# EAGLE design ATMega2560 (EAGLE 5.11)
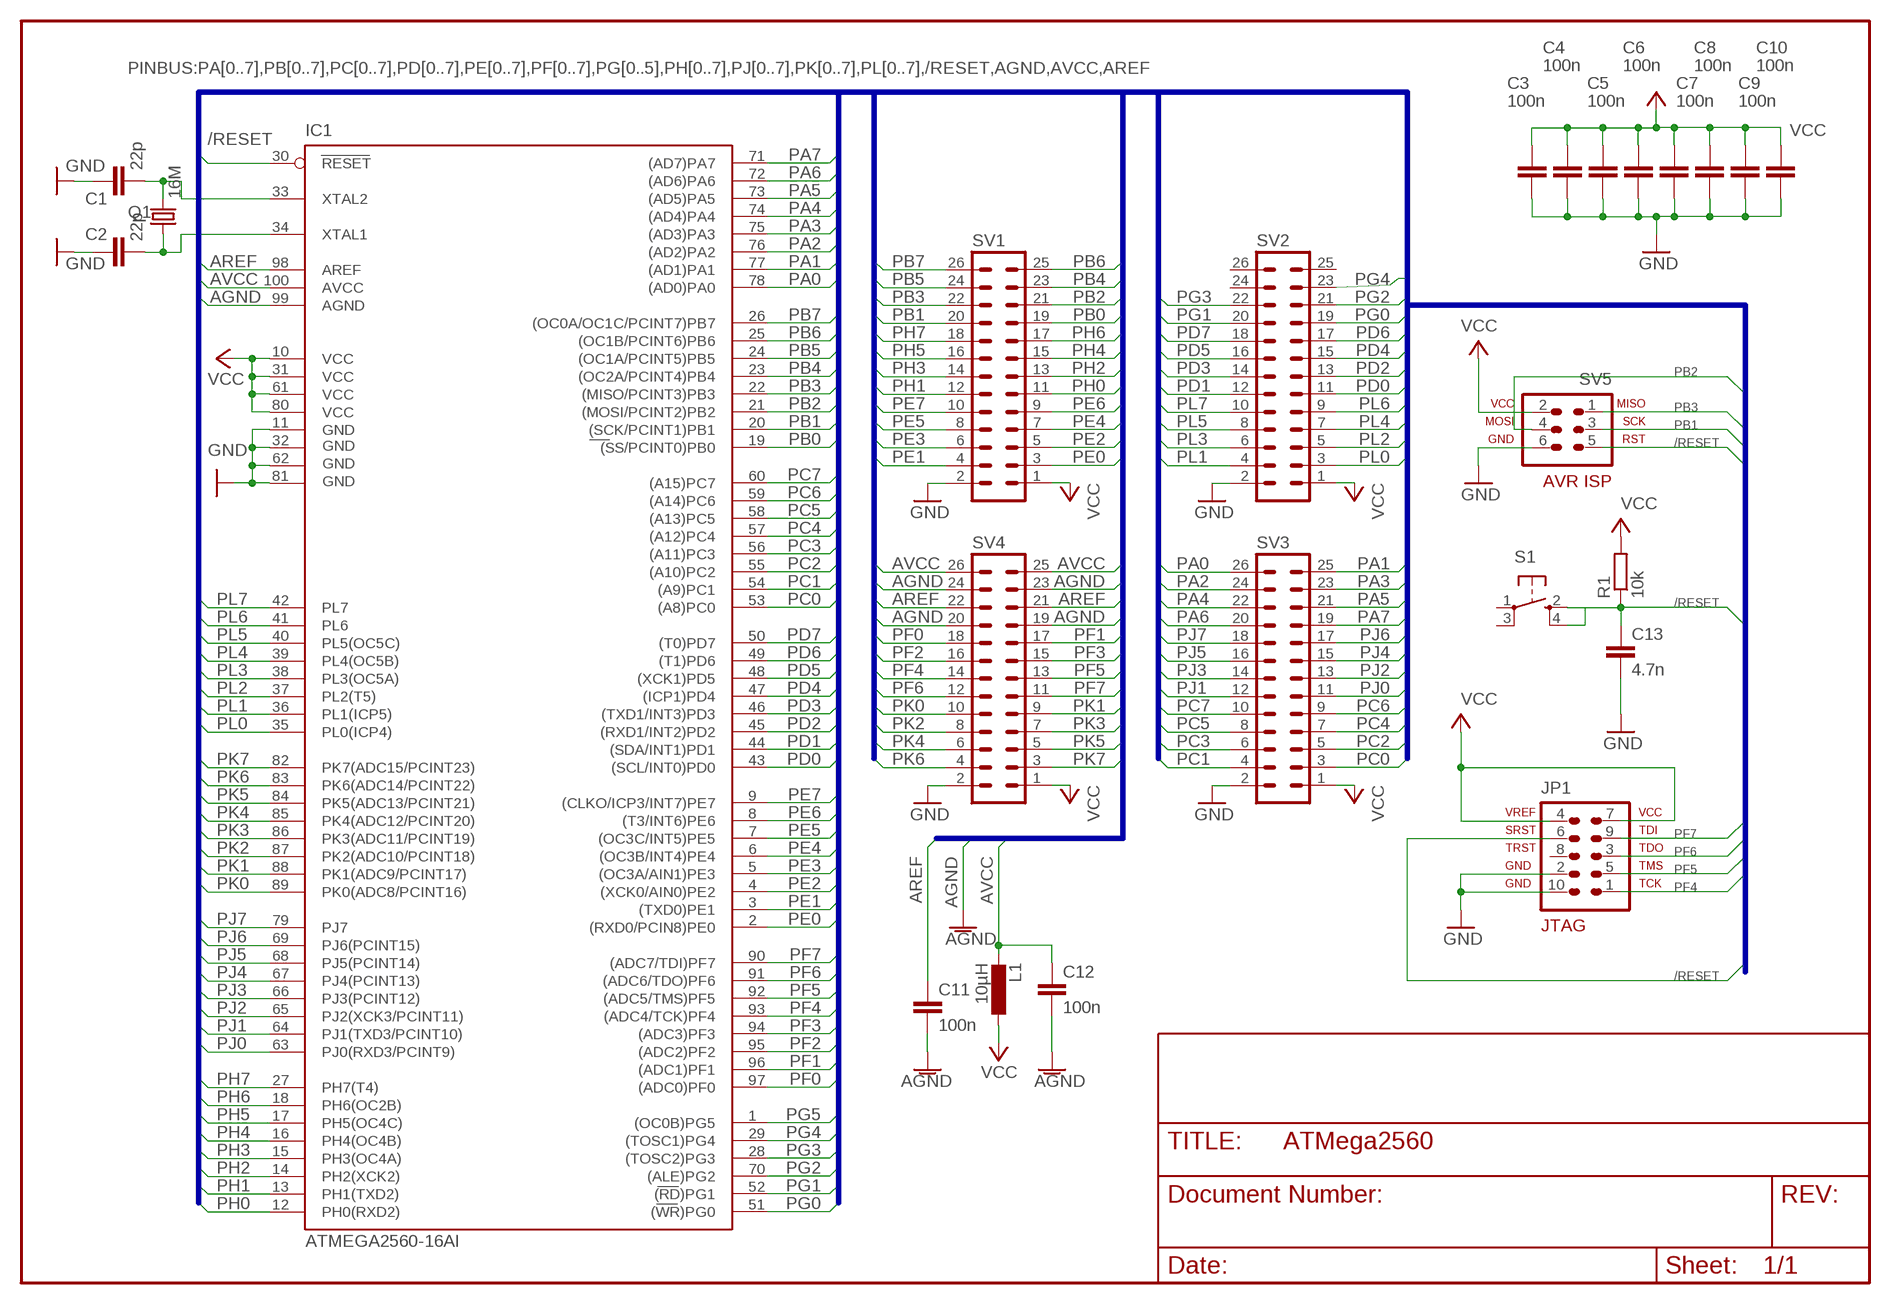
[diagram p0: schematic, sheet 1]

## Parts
C1  22p  C-EUC0402  [C0402]
C2  22p  C-EUC0402  [C0402]
C3  100n  C-EUC0402  [C0402]
C4  100n  C-EUC0402  [C0402]
C5  100n  C-EUC0402  [C0402]
C6  100n  C-EUC0402  [C0402]
C7  100n  C-EUC0402  [C0402]
C8  100n  C-EUC0402  [C0402]
C9  100n  C-EUC0402  [C0402]
C10  100n  C-EUC0402  [C0402]
C11  100n  C-EUC0402  [C0402]
C12  100n  C-EUC0402  [C0402]
C13  4.7n  C-EUC0402  [C0402]
IC1  ATMEGA2560-16AI  [TQFP100]
JP1  AVR-JTAG-10-R  [AVR-JTAG-10R]
L1  10µH  L-EUL1812  [L1812]
Q1  16M  CRYTALHC49S  [HC49/S]
R1  10k  R-EU_R0805  [R0805]
S1  10-XX  [B3S-1XXX]
SV1  MA13-2  [MA13-2]
SV2  MA13-2  [MA13-2]
SV3  MA13-2  [MA13-2]
SV4  MA13-2  [MA13-2]
SV5  AVR-ISP-6HORZ  [AVR-ISP-6R]

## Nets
/RESET: C13.1 IC1.30(RESET) JP1.6 R1.1 S1.2 S1.4 SV5.5
AGND: C11.2 C12.2 IC1.99(AGND) SV4.19 SV4.20 SV4.23 SV4.24
AREF: C11.1 IC1.98(AREF) SV4.21 SV4.22
AVCC: C12.1 IC1.100(AVCC) L1.2 SV4.25 SV4.26
GND: C1.1 C2.1 C3.2 C4.2 C5.2 C6.2 C7.2 C8.2 C9.2 C10.2 C13.2 IC1.11(GND) IC1.32(GND1) IC1.62(GND2) IC1.81(GND3) JP1.2 JP1.10 SV1.2 SV2.2 SV3.2 SV4.2 SV5.6
N$1: C1.2 IC1.33(XTAL2) Q1.2
N$2: C2.2 IC1.34(XTAL1) Q1.1
PA0: IC1.78((AD0)PA0) SV3.26
PA1: IC1.77((AD1)PA1) SV3.25
PA2: IC1.76((AD2)PA2) SV3.24
PA3: IC1.75((AD3)PA3) SV3.23
PA4: IC1.74((AD4)PA4) SV3.22
PA5: IC1.73((AD5)PA5) SV3.21
PA6: IC1.72((AD6)PA6) SV3.20
PA7: IC1.71((AD7)PA7) SV3.19
PB0: IC1.19((SS/PCINT0)PB0) SV1.19
PB1: IC1.20((SCK/PCINT1)PB1) SV1.20 SV5.3
PB2: IC1.21((MOSI/PCINT2)PB2) SV1.21 SV5.4
PB3: IC1.22((MISO/PCINT3)PB3) SV1.22 SV5.1
PB4: IC1.23((OC2A/PCINT4)PB4) SV1.23
PB5: IC1.24((OC1A/PCINT5)PB5) SV1.24
PB6: IC1.25((OC1B/PCINT6)PB6) SV1.25
PB7: IC1.26((OC0A/OC1C/PCINT7)PB7) SV1.26
PC0: IC1.53((A8)PC0) SV3.3
PC1: IC1.54((A9)PC1) SV3.4
PC2: IC1.55((A10)PC2) SV3.5
PC3: IC1.56((A11)PC3) SV3.6
PC4: IC1.57((A12)PC4) SV3.7
PC5: IC1.58((A13)PC5) SV3.8
PC6: IC1.59((A14)PC6) SV3.9
PC7: IC1.60((A15)PC7) SV3.10
PD0: IC1.43((SCL/INT0)PD0) SV2.11
PD1: IC1.44((SDA/INT1)PD1) SV2.12
PD2: IC1.45((RXD1/INT2)PD2) SV2.13
PD3: IC1.46((TXD1/INT3)PD3) SV2.14
PD4: IC1.47((ICP1)PD4) SV2.15
PD5: IC1.48((XCK1)PD5) SV2.16
PD6: IC1.49((T1)PD6) SV2.17
PD7: IC1.50((T0)PD7) SV2.18
PE0: IC1.2((RXD0/PCIN8)PE0) SV1.3
PE1: IC1.3((TXD0)PE1) SV1.4
PE2: IC1.4((XCK0/AIN0)PE2) SV1.5
PE3: IC1.5((OC3A/AIN1)PE3) SV1.6
PE4: IC1.6((OC3B/INT4)PE4) SV1.7
PE5: IC1.7((OC3C/INT5)PE5) SV1.8
PE6: IC1.8((T3/INT6)PE6) SV1.9
PE7: IC1.9((CLKO/ICP3/INT7)PE7) SV1.10
PF0: IC1.97((ADC0)PF0) SV4.18
PF1: IC1.96((ADC1)PF1) SV4.17
PF2: IC1.95((ADC2)PF2) SV4.16
PF3: IC1.94((ADC3)PF3) SV4.15
PF4: IC1.93((ADC4/TCK)PF4) JP1.1 SV4.14
PF5: IC1.92((ADC5/TMS)PF5) JP1.5 SV4.13
PF6: IC1.91((ADC6/TDO)PF6) JP1.3 SV4.12
PF7: IC1.90((ADC7/TDI)PF7) JP1.9 SV4.11
PG0: IC1.51((WR)PG0) SV2.19
PG1: IC1.52((RD)PG1) SV2.20
PG2: IC1.70((ALE)PG2) SV2.21
PG3: IC1.28((TOSC2)PG3) SV2.22
PG4: IC1.29((TOSC1)PG4) SV2.23
PG5: IC1.1((OC0B)PG5)
PH0: IC1.12(PH0(RXD2)) SV1.11
PH1: IC1.13(PH1(TXD2)) SV1.12
PH2: IC1.14(PH2(XCK2)) SV1.13
PH3: IC1.15(PH3(OC4A)) SV1.14
PH4: IC1.16(PH4(OC4B)) SV1.15
PH5: IC1.17(PH5(OC4C)) SV1.16
PH6: IC1.18(PH6(OC2B)) SV1.17
PH7: IC1.27(PH7(T4)) SV1.18
PJ0: IC1.63(PJ0(RXD3/PCINT9)) SV3.11
PJ1: IC1.64(PJ1(TXD3/PCINT10)) SV3.12
PJ2: IC1.65(PJ2(XCK3/PCINT11)) SV3.13
PJ3: IC1.66(PJ3(PCINT12)) SV3.14
PJ4: IC1.67(PJ4(PCINT13)) SV3.15
PJ5: IC1.68(PJ5(PCINT14)) SV3.16
PJ6: IC1.69(PJ6(PCINT15)) SV3.17
PJ7: IC1.79(PJ7) SV3.18
PK0: IC1.89(PK0(ADC8/PCINT16)) SV4.10
PK1: IC1.88(PK1(ADC9/PCINT17)) SV4.9
PK2: IC1.87(PK2(ADC10/PCINT18)) SV4.8
PK3: IC1.86(PK3(ADC11/PCINT19)) SV4.7
PK4: IC1.85(PK4(ADC12/PCINT20)) SV4.6
PK5: IC1.84(PK5(ADC13/PCINT21)) SV4.5
PK6: IC1.83(PK6(ADC14/PCINT22)) SV4.4
PK7: IC1.82(PK7(ADC15/PCINT23)) SV4.3
PL0: IC1.35(PL0(ICP4)) SV2.3
PL1: IC1.36(PL1(ICP5)) SV2.4
PL2: IC1.37(PL2(T5)) SV2.5
PL3: IC1.38(PL3(OC5A)) SV2.6
PL4: IC1.39(PL4(OC5B)) SV2.7
PL5: IC1.40(PL5(OC5C)) SV2.8
PL6: IC1.41(PL6) SV2.9
PL7: IC1.42(PL7) SV2.10
VCC: C3.1 C4.1 C5.1 C6.1 C7.1 C8.1 C9.1 C10.1 IC1.10(VCC) IC1.31(VCC1) IC1.61(VCC2) IC1.80(VCC3) JP1.4 JP1.7 L1.1 R1.2 SV1.1 SV2.1 SV3.1 SV4.1 SV5.2
Unconnected: JP1.8 S1.1 S1.3 SV2.24 SV2.25 SV2.26

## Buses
PINBUS:PA[0..7],PB[0..7],PC[0..7],PD[0..7],PE[0..7],PF[0..7],PG[0..5],PH[0..7],PJ[0..7],PK[0..7],PL[0..7],/RESET,AGND,AVCC,AREF

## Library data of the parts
C1-C13 = rcl:C-EU: CAPACITOR, European symbol
IC1 = atmel-2005:ATMEGA*: MICROCONTROLLER 64/128/256 Kbytes FLASH 4 Kbytes EEPROM 8 Kbytes SRAM 86 General Purpose I/O pins 12-channels16-bit PWM 4 x Serial USARTs 16-channels 10-bit A/D
JP1 = avr-7:AVR-JTAG-10: AVR JTAG Debug/Programming Header
L1 = rcl:L-EU: INDUCTOR, European symbol
Q1 = crystal:CRYTAL: CRYSTAL
R1 = rcl:R-EU_: RESISTOR, European symbol
S1 = Masterarbeit:10-XX: OMRON SWITCH
SV1-SV4 = con-lstb:MA13-2: PIN HEADER
SV5 = avr-7:AVR-ISP-6: AVR ISP-6 Serial Programming Header

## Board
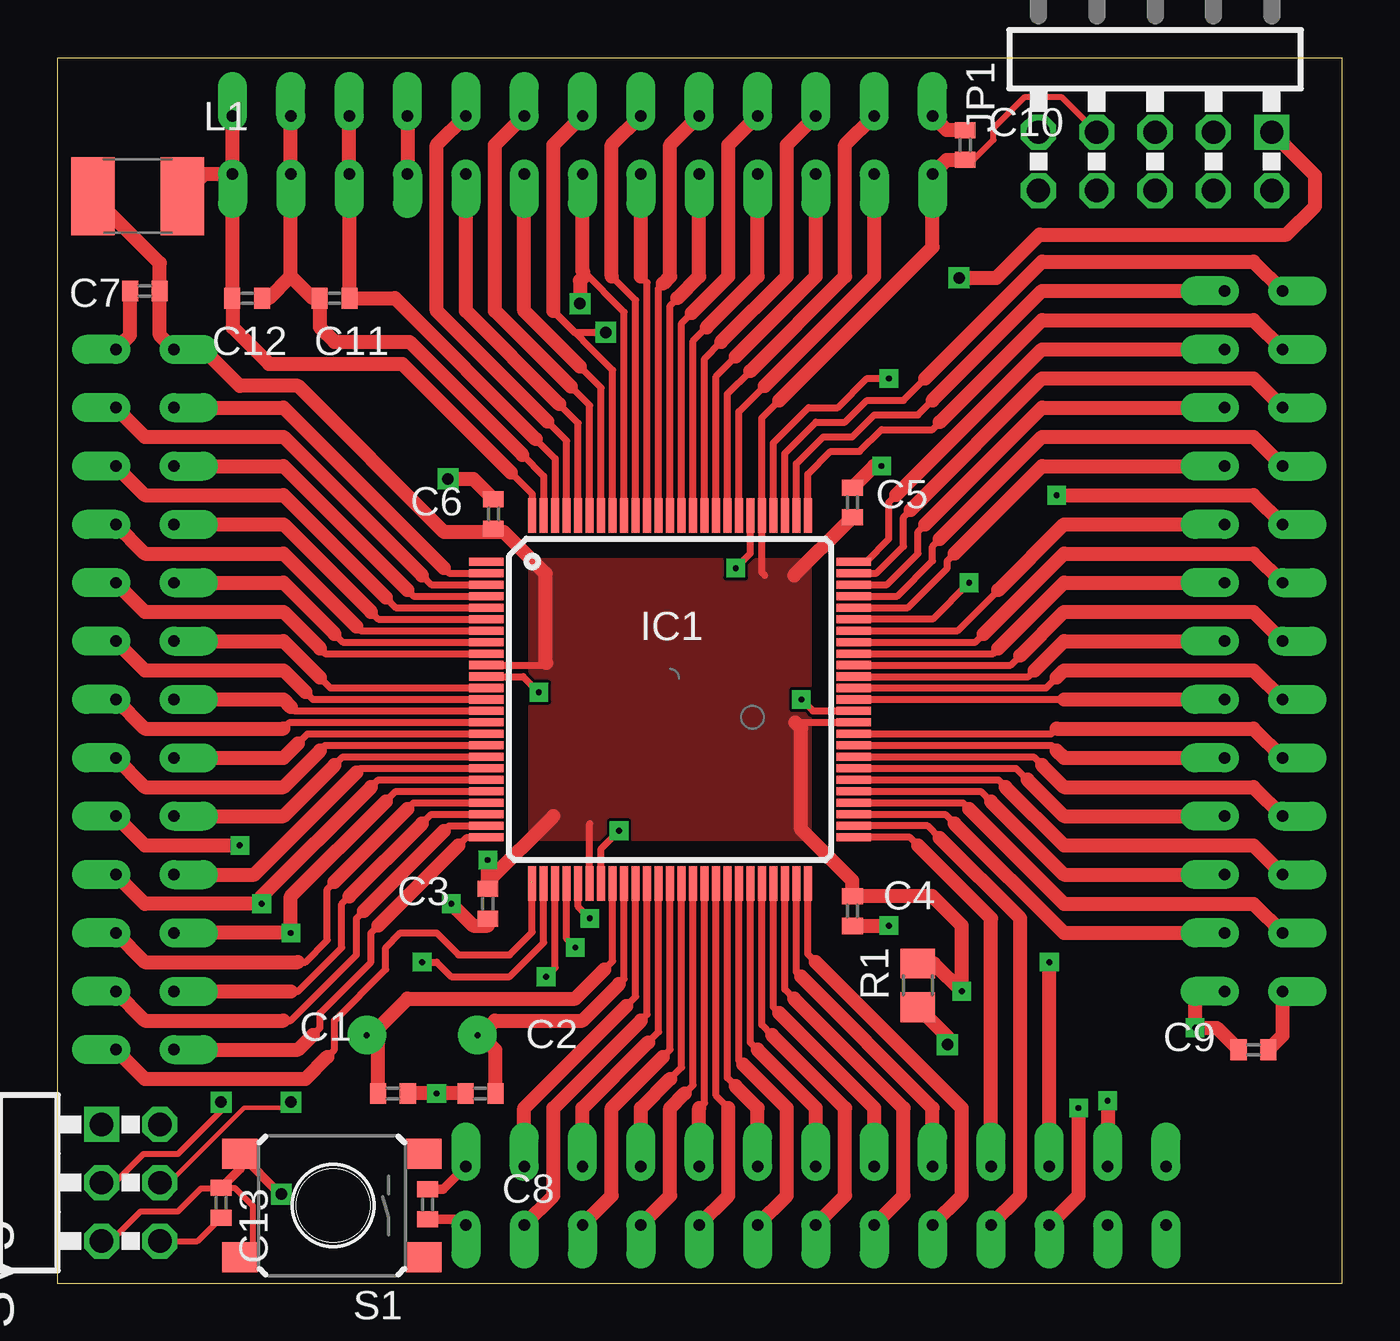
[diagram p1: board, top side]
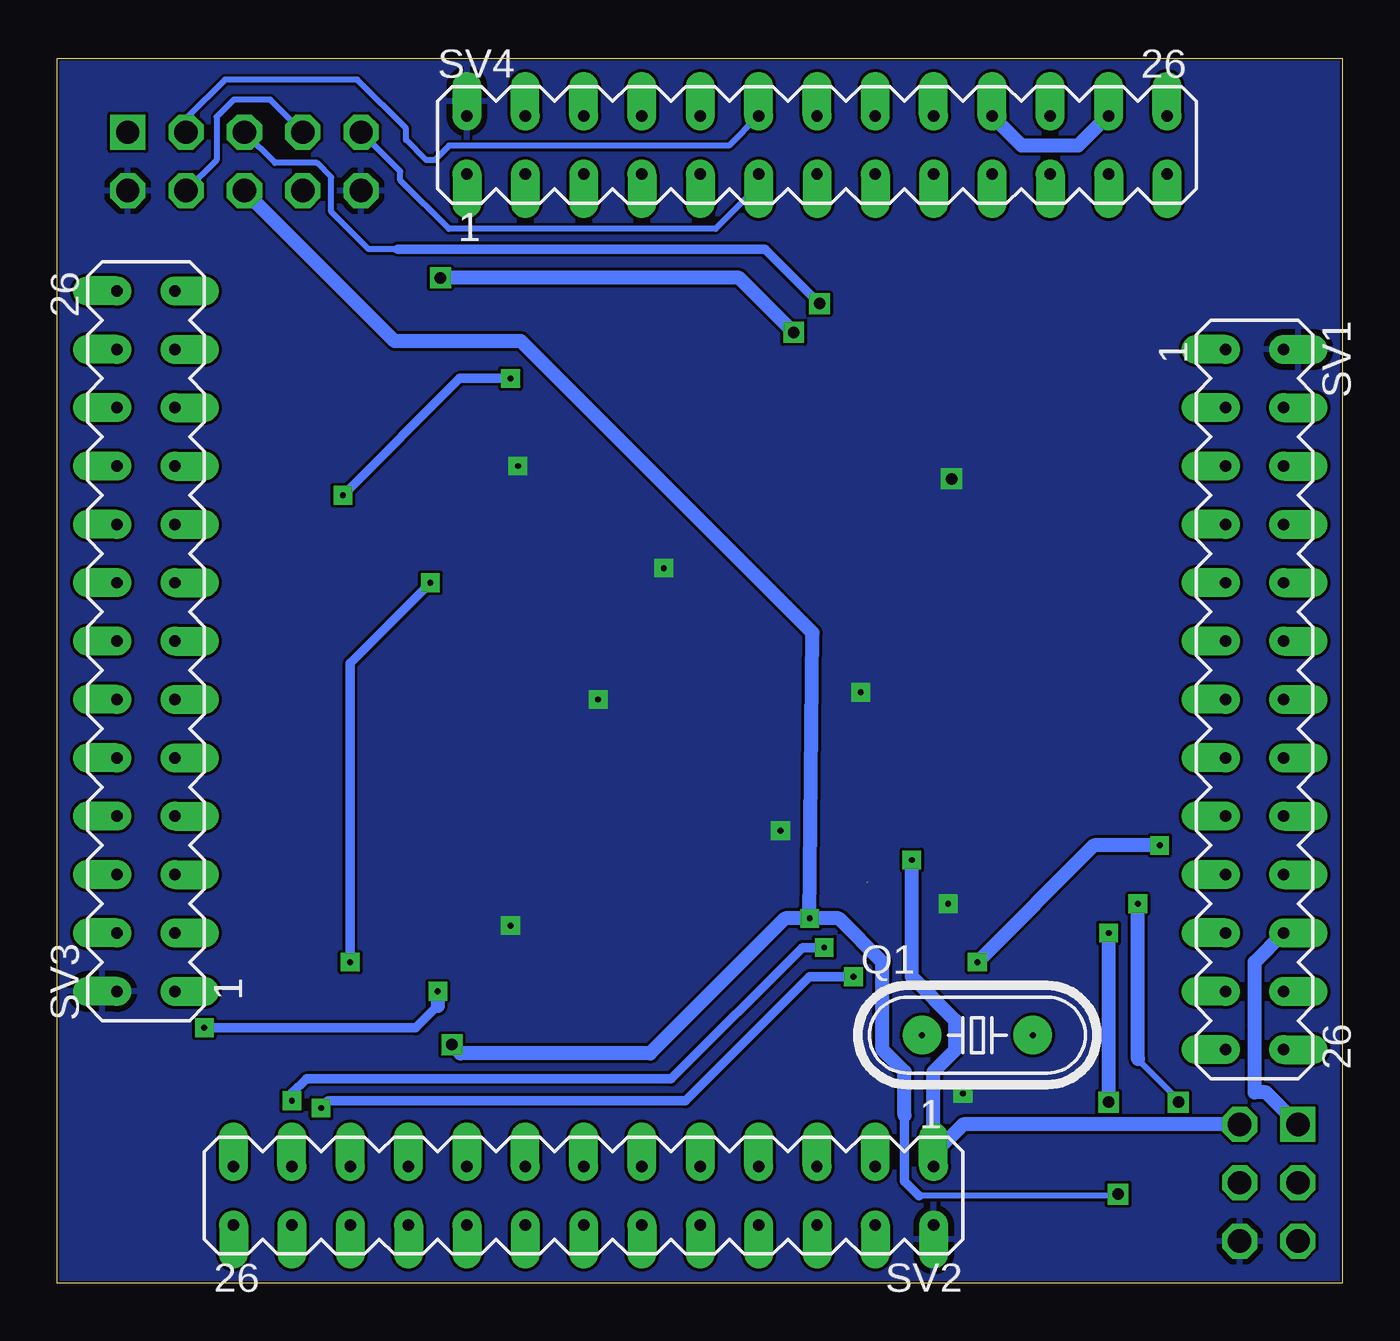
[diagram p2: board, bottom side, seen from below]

Size 55.92 x 53.3 mm. Coordinates in mm from the lower left corner, seen from the top.
Outline: 0,0 55.92,0 55.92,53.3 0,53.3 0,0
Copper layers (1*16): Top 0.035mm / dielectric 1.5mm / Bottom 0.035mm
Design rules "default *": minimum track width 7mil, minimum drill 10mil, track to track 5mil, track to pad 5mil, pad to pad 5mil, via to via 5mil, smd to smd 5mil, copper to edge 4mil, drill to drill 8mil, minimum pad ring 10mil, minimum via ring 8mil, stop-mask expansion 4mil, vias tented up to drill 0mil, thermal gap 10mil

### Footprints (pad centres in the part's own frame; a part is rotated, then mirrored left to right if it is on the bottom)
C0402 = smd 0.7 x 0.9: 1 -0.65,0; 2 0.65,0
TQFP100 = smd 1.5 x 0.35: 1 -8,6; 2 -8,5.5; 3 -8,5; 4 -8,4.5; 5 -8,4; 6 -8,3.5; 7 -8,3; 8 -8,2.5; 9 -8,2; 10 -8,1.5; 11 -8,1; 12 -8,0.5; 13 -8,0; 14 -8,-0.5; 15 -8,-1; 16 -8,-1.5; 17 -8,-2; 18 -8,-2.5; 19 -8,-3; 20 -8,-3.5; 21 -8,-4; 22 -8,-4.5; 23 -8,-5; 24 -8,-5.5; 25 -8,-6; 51 8,-6; 52 8,-5.5; 53 8,-5; 54 8,-4.5; 55 8,-4; 56 8,-3.5; 57 8,-3; 58 8,-2.5; 59 8,-2; 60 8,-1.5; 61 8,-1; 62 8,-0.5; 63 8,0; 64 8,0.5; 65 8,1; 66 8,1.5; 67 8,2; 68 8,2.5; 69 8,3; 70 8,3.5; 71 8,4; 72 8,4.5; 73 8,5; 74 8,5.5; 75 8,6 | smd 0.35 x 1.5: 26 -6,-8; 27 -5.5,-8; 28 -5,-8; 29 -4.5,-8; 30 -4,-8; 31 -3.5,-8; 32 -3,-8; 33 -2.5,-8; 34 -2,-8; 35 -1.5,-8; 36 -1,-8; 37 -0.5,-8; 38 0,-8; 39 0.5,-8; 40 1,-8; 41 1.5,-8; 42 2,-8; 43 2.5,-8; 44 3,-8; 45 3.5,-8; 46 4,-8; 47 4.5,-8; 48 5,-8; 49 5.5,-8; 50 6,-8; 76 6,8; 77 5.5,8; 78 5,8; 79 4.5,8; 80 4,8; 81 3.5,8; 82 3,8; 83 2.5,8; 84 2,8; 85 1.5,8; 86 1,8; 87 0.5,8; 88 0,8; 89 -0.5,8; 90 -1,8; 91 -1.5,8; 92 -2,8; 93 -2.5,8; 94 -3,8; 95 -3.5,8; 96 -4,8; 97 -4.5,8; 98 -5,8; 99 -5.5,8; 100 -6,8
AVR-JTAG-10R = drill 1.016 square: 1 -5.08,-1.27 | drill 1.016 octagon: 2 -5.08,1.27; 3 -2.54,-1.27; 4 -2.54,1.27; 5 0,-1.27; 6 0,1.27; 7 2.54,-1.27; 8 2.54,1.27; 10 5.08,1.27 | drill 1.016 pad 1.422 octagon: 9 5.08,-1.27
L1812 = smd 1.9 x 3.4: 1 -1.95,0; 2 1.95,0
HC49/S = drill 0.254 pad 1.676 round: 1 -2.413,0; 2 2.413,0
R0805 = smd 1.3 x 1.5: 1 -0.95,0; 2 0.95,0
B3S-1XXX = smd 1.55 x 1.3: 1 -3.95,2.25; 2 4.05,2.25; 3 -3.95,-2.25; 4 4.05,-2.25
MA13-2 = drill 0.5 pad 1.27 offset: 1 -15.24,-1.27; 2 -15.24,1.27; 3 -12.7,-1.27; 4 -12.7,1.27; 5 -10.16,-1.27; 6 -10.16,1.27; 7 -7.62,-1.27; 8 -7.62,1.27; 9 -5.08,-1.27; 10 -5.08,1.27; 11 -2.54,-1.27; 12 -2.54,1.27; 13 0,-1.27; 14 0,1.27; 15 2.54,-1.27; 16 2.54,1.27; 17 5.08,-1.27; 18 5.08,1.27; 19 7.62,-1.27; 20 7.62,1.27; 21 10.16,-1.27; 22 10.16,1.27; 23 12.7,-1.27; 24 12.7,1.27; 25 15.24,-1.27; 26 15.24,1.27
AVR-ISP-6R = drill 1.016 square: 1 -2.54,-1.27 | drill 1.016 octagon: 2 -2.54,1.27; 3 0,-1.27; 4 0,1.27; 5 2.54,-1.27; 6 2.54,1.27

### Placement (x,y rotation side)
C1  14.61,8.26 180 top
C2  18.41,8.26 0 top
C3  18.73,16.51 270 top
C4  34.61,16.19 270 top
C5  34.61,33.97 90 top
C6  18.98,33.47 90 top
C7  3.81,43.18 180 top
C8  16.11,3.44 270 top
C9  52.07,10.16 0 top
C10  39.52,49.53 90 top
C11  12.06,42.86 180 top
C12  8.26,42.86 0 top
C13  7.12,3.5 270 top
IC1  26.67,25.4 0 top
JP1  47.78,48.81 180 top
L1  3.49,47.31 0 top
Q1  15.88,10.79 0 bottom
R1  37.45,12.96 90 top
S1  12,3.38 180 top
SV1  3.81,25.4 270 bottom
SV2  33.02,3.81 180 bottom
SV3  52.07,27.94 90 bottom
SV4  22.86,49.53 0 bottom
SV5  3.19,4.37 270 top

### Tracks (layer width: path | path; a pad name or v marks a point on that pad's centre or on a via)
/RESET  (via drill 0.25 pad 0.81, 0.5)
  Top 0.254: SV5.5 2.33,1.83 3.62,3.12 5.25,3.12 6.25,4.12 7.1,4.12 C13.1 7.72,4.15 8.5,3.38 8.5,1.68 S1.2
  Top 0.305: IC1.30 22.67,16.38 v23.18,15.88
  Top 0.406: v9.75,3.88 9.7,3.88 S1.4 7.95,4.97 C13.1
  Top 0.61: v38.75,10.38 38.75,10.71 R1.1
  Bottom 0.254: 18.41,3.81 9.81,3.81 v9.75,3.88
  Bottom 0.406: 18.41,3.81 19.05,4.45 19.05,7.3
  Bottom 0.61: v23.18,15.88 21.91,15.88 20,13.97 20,10.16 19.05,9.21 19.05,7.3 | v23.18,15.88 23.05,28.3 35.75,41 41.24,41 JP1.6 | v23.18,15.88 24.25,15.88 30.12,10 38.38,10 v38.75,10.38
AGND
  Top 0.305: IC1.99 21.17,35.12 20.24,36.04
  Top 0.61: 10.16,51.12 SV4.24 SV4.23 10.16,43.81 | SV4.20 SV4.19 | 20.24,36.04 15.33,40.96 12.06,40.96 11.41,41.61 C11.2 11.11,42.86 10.16,43.81 | 10.16,43.81 9.21,42.86 C12.2
  Bottom 0.61: SV4.20 13.94,49.5 11.5,49.5 10.2,50.8 SV4.24
AREF
  Top 0.305: IC1.98 21.67,35.88 20.82,36.73
  Top 0.61: SV4.21 12.7,47.94 | 20.82,36.73 14.69,42.86 C11.1 12.71,48.24 SV4.21 | SV4.21 SV4.22
AVCC
  Top 0.305: IC1.100 20.67,34.34 19.73,35.28
  Top 0.61: 19.73,35.28 15.01,40.01 9.21,40.01 7.62,41.59 7.62,42.88 | 7.62,42.88 SV4.25 | C12.1 7.62,42.88 | L1.2 6.39,48.26 SV4.25 | SV4.25 SV4.26
GND  (via drill 0.25 pad 0.81, 0.5)
  Top 0.254: SV5.6 6.11,1.83 C13.2
  Top 0.305: IC1.11 20.27,26.4 v20.95,25.72 | IC1.81 30.17,31.76 v29.53,31.11 | IC1.62 32.88,24.9 v32.38,25.4 | IC1.32 23.67,18.91 v24.45,19.68
  Top 0.406: C8.2 17.54,2.79 SV2.2
  Top 0.61: C3.2 18.73,15.56 18.1,15.56 v17.14,16.51 | C4.2 34.61,15.56 v36.2,15.56 | C1.1 v16.51,8.26 C2.1 | SV1.2 3.16,41.26 C7.2 | v35.88,35.56 35.55,35.56 C5.2 | SV4.2 38.72,50.18 C10.2 | C9.2 53.34,10.78 SV3.2 | C6.2 18.11,35 v17,35
  pour Bottom: 0,53.17 55.92,53.3 55.92,0 0,0
N$1
  Top 0.305: IC1.33 24.17,14.01 23.81,13.65
  Top 0.61: 23.81,13.65 22.54,12.38 15.24,12.38 13.65,10.79 | 13.65,10.79 Q1.2 | 13.65,10.79 13.96,10.49 C1.2
N$2
  Top 0.305: IC1.34 24.67,13.24 24.45,13.02
  Top 0.61: 24.45,13.02 22.86,11.43 19.05,11.43 18.41,10.79 | 18.41,10.79 Q1.1 | 18.41,10.79 19.07,10.14 C2.2
PA0
  Top 0.305: IC1.78 31.67,36.12 33.02,37.47 34.29,37.47 35.24,38.42 36.83,38.42 37.78,39.37
  Top 0.61: SV3.26 52.07,44.45 42.86,44.45 37.78,39.37
PA1
  Top 0.305: IC1.77 32.17,35.66 33.34,36.83 34.61,36.83 35.56,37.78 37.47,37.78 38.1,38.42
  Top 0.61: SV3.25 42.86,43.18 38.1,38.42
PA2
  Top 0.305: IC1.76 32.67,35.21 33.66,36.2 34.92,36.2 35.88,37.15 38.1,37.15 38.42,37.47
  Top 0.61: SV3.24 52.07,41.91 42.86,41.91 38.42,37.47
PA3
  Top 0.305: IC1.75 35.21,31.4 36.2,32.38 36.2,33.97 36.51,34.29
  Top 0.61: SV3.23 42.86,40.64 36.51,34.29
PA4
  Top 0.305: IC1.74 35.66,30.9 36.83,32.07 36.83,33.34 37.15,33.66
  Top 0.61: SV3.22 52.07,39.37 42.86,39.37 37.15,33.66
PA5
  Top 0.305: IC1.73 36.12,30.4 37.47,31.75 37.47,32.7 37.78,33.02
  Top 0.61: SV3.21 42.86,38.1 37.78,33.02
PA6
  Top 0.305: IC1.72 36.57,29.9 38.1,31.43 38.1,32.07 38.42,32.38
  Top 0.61: SV3.20 52.07,36.83 42.86,36.83 38.42,32.38
PA7
  Top 0.305: IC1.71 37.02,29.4 38.73,31.11 38.73,31.43 39.05,31.75
  Top 0.61: SV3.19 42.86,35.56 39.05,31.75
PB0
  Top 0.305: IC1.19 13.19,22.4 13.02,22.23
  Top 0.61: SV1.19 8.57,17.78 13.02,22.23
PB1  (via drill 0.25 pad 0.81, 0.5)
  Top 0.254: SV5.3 2.5,4.37 3.75,5.62 5.25,5.62 7.12,7.5 v7.12,7.88
  Top 0.305: IC1.20 13.96,21.9 13.65,21.59
  Top 0.61: SV1.20 3.81,16.51 v8.89,16.51 8.89,16.83 13.65,21.59
  Bottom 0.254: v7.12,7.88 7.12,7.99 8.89,9.75
  Bottom 0.61: 8.89,9.75 v8.89,16.51
PB2  (via drill 0.25 pad 0.81, 0.5)
  Top 0.2: 9.91,7.62 8.12,7.62 5,4.5
  Top 0.254: 9.91,7.62 v10.16,7.88 | 5,4.5 4.59,4.5 SV5.4
  Top 0.305: IC1.21 14.73,21.4 14.29,20.95
  Top 0.61: SV1.21 v10.16,15.24 10.16,16.83 14.29,20.95
  Bottom 0.61: 10.16,8 v10.16,7.88 v10.16,15.24
PB3
  Top 0.305: 10.48,13.97 10.79,13.97 11.75,14.92 11.75,17.14 12.06,17.46 | IC1.22 15.5,20.9 15.24,20.64
  Top 0.61: SV1.22 3.81,13.97 10.48,13.97 | 12.06,17.46 15.24,20.64
  Bottom 0.61: SV1.22 3.81,13.97 3.81,8.3 3.31,8.3 SV5.1
PB4
  Top 0.305: 10.16,12.7 10.48,12.7 12.38,14.61 12.38,16.51 12.7,16.83 | IC1.23 16.27,20.4 15.88,20
  Top 0.61: SV1.23 10.16,12.7 | 12.7,16.83 15.88,20
PB5
  Top 0.305: 9.84,11.43 10.16,11.43 13.02,14.29 13.02,15.88 13.34,16.19 | IC1.24 17.04,19.9 16.83,19.68
  Top 0.61: SV1.24 3.81,11.43 9.84,11.43 | 13.34,16.19 16.83,19.68
PB6
  Top 0.305: 11.11,10.79 11.43,11.11 11.43,11.75 13.65,13.97 13.65,15.24 13.97,15.56 | IC1.25 17.81,19.4 17.46,19.05
  Top 0.61: SV1.25 10.48,10.16 11.11,10.79 | 13.97,15.56 17.46,19.05
PB7  (1 unrouted)
  Top 0.305: 20.67,17.43 IC1.26 20.67,15.27 19.68,14.29 17.46,14.29 16.51,15.24 14.92,15.24 14.29,14.61 14.29,13.65 12.06,11.43 12.06,10.16 11.75,9.84 | 20.64,17.46 20.67,17.46
  Top 0.61: SV1.26 3.81,8.89 10.79,8.89 11.75,9.84
PC0
  Top 0.305: IC1.53 38.66,20.4 39.05,20
  Top 0.61: SV3.3 43.81,15.24 39.05,20
PC1
  Top 0.305: IC1.54 39.42,20.9 39.69,20.64
  Top 0.61: SV3.4 52.07,16.51 43.81,16.51 39.69,20.64
PC2
  Top 0.305: IC1.55 40.2,21.4 40.64,20.95
  Top 0.61: SV3.5 43.81,17.78 40.64,20.95
PC3
  Top 0.305: IC1.56 40.97,21.9 41.27,21.59
  Top 0.61: SV3.6 52.07,19.05 43.81,19.05 41.27,21.59
PC4
  Top 0.305: IC1.57 41.73,22.4 42.23,21.91
  Top 0.61: SV3.7 43.81,20.32 42.23,21.91
PC5
  Top 0.305: IC1.58 42.51,22.9 42.86,22.54
  Top 0.61: SV3.8 52.07,21.59 43.81,21.59 42.86,22.54
PC6
  Top 0.305: IC1.59 43.27,23.4 43.5,23.18
  Top 0.61: SV3.9 43.81,22.86 43.5,23.18
PC7
  Top 0.305: IC1.60 43.27,23.9 43.5,24.13
  Top 0.61: SV3.10 52.07,24.13 43.5,24.13
PD0
  Top 0.305: IC1.43 29.17,8.93 29.53,8.57
  Top 0.61: 29.53,8.57 30.48,7.62 SV2.11
PD1
  Top 0.305: IC1.44 29.67,9.7 29.84,9.53
  Top 0.61: SV2.12 31.75,3.81 31.75,7.62 29.84,9.53
PD2
  Top 0.305: IC1.45 30.17,10.47 30.48,10.16
  Top 0.61: 30.48,10.16 33.02,7.62 SV2.13
PD3
  Top 0.305: IC1.46 30.67,11.24 31.11,10.79
  Top 0.61: SV2.14 34.29,3.81 34.29,7.62 31.11,10.79
PD4
  Top 0.305: IC1.47 31.17,12.01 31.43,11.75
  Top 0.61: 31.43,11.75 35.56,7.62 SV2.15
PD5
  Top 0.305: IC1.48 31.67,12.78 32.07,12.38
  Top 0.61: SV2.16 36.83,3.81 36.83,7.62 32.07,12.38
PD6
  Top 0.305: IC1.49 32.17,13.55 32.38,13.34
  Top 0.61: 32.38,13.34 38.1,7.62 SV2.17
PD7
  Top 0.305: IC1.50 32.67,14.32 33.02,13.97
  Top 0.61: 33.02,13.97 39.37,7.62 39.37,3.81 SV2.18
PE0
  Top 0.305: IC1.2 17.04,30.9 16.83,31.11
  Top 0.61: SV1.3 9.84,38.1 16.83,31.11
PE1
  Top 0.305: IC1.3 16.27,30.4 15.88,30.8
  Top 0.61: SV1.4 3.81,36.83 9.84,36.83 15.88,30.8
PE2
  Top 0.305: IC1.4 15.5,29.9 15.24,30.16
  Top 0.61: SV1.5 9.84,35.56 15.24,30.16
PE3
  Top 0.305: IC1.5 14.73,29.4 14.29,29.84
  Top 0.61: SV1.6 3.81,34.29 9.84,34.29 14.29,29.84
PE4
  Top 0.305: IC1.6 13.96,28.9 13.65,29.21
  Top 0.61: SV1.7 9.84,33.02 13.65,29.21
PE5
  Top 0.305: IC1.7 13.19,28.4 13.02,28.57
  Top 0.61: SV1.8 3.81,31.75 9.84,31.75 13.02,28.57
PE6
  Top 0.305: IC1.8 12.42,27.9 12.06,28.26
  Top 0.61: SV1.9 9.84,30.48 12.06,28.26
PE7
  Top 0.305: IC1.9 11.65,27.4 11.43,27.62
  Top 0.61: SV1.10 3.81,29.21 9.84,29.21 11.43,27.62
PF0
  Top 0.305: IC1.97 22.17,36.66 21.33,37.49
  Top 0.61: SV4.18 16.51,49.53 16.51,42.31 21.33,37.49
PF1
  Top 0.305: IC1.96 22.67,37.42 21.84,38.26
  Top 0.61: SV4.17 17.78,42.31 21.84,38.26
PF2
  Top 0.305: IC1.95 23.17,38.2 22.35,39.02
  Top 0.61: SV4.16 19.05,49.53 19.05,42.31 22.35,39.02
PF3
  Top 0.305: IC1.94 23.67,38.97 22.73,39.9
  Top 0.61: SV4.15 20.32,42.31 22.73,39.9
PF4  (via drill 0.5)
  Top 0.305: IC1.93 24.17,39.73 21.59,42.31 | SV4.14 21.62,49.56 21.62,42.25 22.5,41.38 v23.88,41.38
  Top 0.61: SV4.14 21.59,49.53 21.59,42.31 | v39.25,43.75 40.88,43.75 42.75,45.62 53.5,45.62 54.75,46.88 54.75,48.2 JP1.1
  Bottom 0.61: v23.88,41.38 26.25,43.75 v39.25,43.75
PF5  (via drill 0.5)
  Top 0.305: IC1.92 24.67,42.26 22.88,44.05 | 22.88,43.75 22.93,43.75
  Top 0.61: SV4.13 22.86,44.06 22.88,44.05 22.88,43.75 22.75,43.62 v22.75,42.62
  Bottom 0.254: 41.12,45 42.38,45 44,46.62 44,48.12 44.62,48.75 46.45,48.75 JP1.5
  Bottom 0.406: v22.75,42.62 25.12,45 41.12,45
PF6
  Top 0.305: IC1.91 25.17,42.77 24.13,43.81
  Top 0.61: SV4.12 24.13,49.53 24.13,43.81
  Bottom 0.254: SV4.12 26.7,49.5 38.88,49.5 39.5,48.88 39.88,48.88 40.75,49.75 40.75,50.25 42.88,52.38 48.62,52.38 50.25,50.75 50.25,50.16 JP1.3
PF7
  Top 0.305: IC1.90 25.67,43.55 25.4,43.81
  Top 0.61: 25.4,43.81 SV4.11
  Bottom 0.254: SV4.11 25.4,47.75 27.27,45.88 38.88,45.88 41,48 41,48.38 JP1.9
PG0
  Top 0.305: IC1.51 37.12,19.4 37.47,19.05
  Top 0.61: SV2.19 40.64,15.88 37.47,19.05
PG1
  Top 0.305: IC1.52 37.88,19.9 38.42,19.37
  Top 0.61: SV2.20 41.91,3.81 41.91,15.88 38.42,19.37
PG2  (via drill 0.25 pad 0.81)
  Top 0.305: IC1.70 38.11,28.9 v39.69,30.48
  Top 0.61: SV2.21 v43.18,13.97
  Bottom 0.406: v43.18,13.97 43.18,26.99 v39.69,30.48
PG3  (via drill 0.25 pad 0.81)
  Top 0.305: IC1.28 21.67,13.73 v21.27,13.34
  Top 0.61: SV2.22 44.45,3.81 v44.45,7.62
  Bottom 0.406: v21.27,13.34 23.18,13.34 28.57,7.94 44.13,7.94 v44.45,7.62
PG4  (via drill 0.25 pad 0.81)
  Top 0.305: IC1.29 22.17,14.98 v22.54,14.61
  Top 0.61: v45.72,7.94 SV2.23
  Bottom 0.406: v22.54,14.61 23.5,14.61 29.21,8.89 45.09,8.89 45.72,8.26 v45.72,7.94
PH0
  Top 0.305: IC1.12 11.88,25.9 11.43,26.35
  Top 0.61: SV1.11 9.84,27.94 11.43,26.35
PH1
  Top 0.305: IC1.13 11.11,25.4 10.79,25.72
  Top 0.61: SV1.12 3.81,26.67 9.84,26.67 10.79,25.72
PH2
  Top 0.305: IC1.14 10.34,24.9 10.16,25.08
  Top 0.61: SV1.13 9.84,25.4 10.16,25.08
PH3
  Top 0.305: IC1.15 10.11,24.4 9.84,24.13
  Top 0.61: SV1.14 3.81,24.13 9.84,24.13
PH4
  Top 0.305: IC1.16 10.88,23.9 10.48,23.5
  Top 0.61: SV1.15 9.84,22.86 10.48,23.5
PH5
  Top 0.305: IC1.17 11.65,23.4 11.43,23.18
  Top 0.61: SV1.16 3.81,21.59 9.84,21.59 11.43,23.18
PH6
  Top 0.305: IC1.18 12.42,22.9 12.06,22.54
  Top 0.61: SV1.17 9.84,20.32 12.06,22.54
PH7  (via drill 0.25 pad 0.81)
  Top 0.305: v15.88,13.97 16.51,13.97 17.14,13.34 19.68,13.34 21.17,14.82 IC1.27
  Top 0.61: SV1.18 3.81,19.05 v7.94,19.05
  Bottom 0.61: v7.94,19.05 10.79,19.05 v15.88,13.97
PJ0
  Top 0.305: IC1.63 43.81,25.4
  Top 0.61: 43.81,25.4 SV3.11
PJ1
  Top 0.305: IC1.64 43.05,25.9 43.5,26.35
  Top 0.61: SV3.12 52.07,26.67 43.81,26.67 43.5,26.35
PJ2
  Top 0.305: IC1.65 42.27,26.4 42.55,26.67
  Top 0.61: SV3.13 43.81,27.94 42.55,26.67
PJ3
  Top 0.305: IC1.66 41.51,26.9 41.91,27.3
  Top 0.61: SV3.14 52.07,29.21 43.81,29.21 41.91,27.3
PJ4
  Top 0.305: IC1.67 40.73,27.4 40.96,27.62
  Top 0.61: SV3.15 43.81,30.48 40.96,27.62
PJ5
  Top 0.305: IC1.68 39.97,27.9 40.32,28.26
  Top 0.61: SV3.16 52.07,31.75 43.81,31.75 40.32,28.26
PJ6
  Top 0.305: IC1.69 39.2,28.4 40.96,30.16
  Top 0.61: SV3.17 43.81,33.02 40.96,30.16
PJ7  (via drill 0.25 pad 0.81)
  Top 0.305: IC1.79 31.17,36.57 32.7,38.1 33.97,38.1 35.24,39.37 v36.2,39.37
  Top 0.61: SV3.18 52.07,34.29 v43.5,34.29
  Bottom 0.406: v36.2,39.37 38.42,39.37 v43.5,34.29
PK0
  Top 0.305: IC1.89 26.17,43.31 26.35,43.5
  Top 0.61: SV4.10 26.67,49.53 26.67,43.81 26.35,43.5
PK1
  Top 0.305: IC1.88 26.67,42.55 26.99,42.86
  Top 0.61: SV4.9 27.94,43.81 26.99,42.86
PK2
  Top 0.305: IC1.87 27.17,41.77 27.62,42.23
  Top 0.61: SV4.8 29.21,49.53 29.21,43.81 27.62,42.23
PK3
  Top 0.305: IC1.86 27.67,41.01 28.26,41.59
  Top 0.61: SV4.7 30.48,43.81 28.26,41.59
PK4
  Top 0.305: IC1.85 28.17,40.23 28.89,40.96
  Top 0.61: SV4.6 31.75,49.53 31.75,43.81 28.89,40.96
PK5
  Top 0.305: IC1.84 28.67,39.47 29.53,40.32
  Top 0.61: SV4.5 33.02,43.81 29.53,40.32
PK6
  Top 0.305: IC1.83 29.17,38.7 30.16,39.69
  Top 0.61: SV4.4 34.29,49.53 34.29,43.81 30.16,39.69
PK7
  Top 0.305: IC1.82 29.67,37.92 30.8,39.05
  Top 0.61: SV4.3 35.56,43.81 30.8,39.05
PL0
  Top 0.305: IC1.35 25.17,12.47 24.77,12.06
  Top 0.61: 24.77,12.06 20.32,7.62 SV2.3
PL1
  Top 0.305: IC1.36 25.67,11.7 25.4,11.43
  Top 0.61: SV2.4 21.59,3.81 21.59,7.62 25.4,11.43
PL2
  Top 0.305: IC1.37 26.17,10.93 25.72,10.48
  Top 0.61: 25.72,10.48 22.86,7.62 SV2.5
PL3
  Top 0.305: IC1.38 26.67,10.16 26.35,9.84
  Top 0.61: SV2.6 24.13,3.81 24.13,7.62 26.35,9.84
PL4
  Top 0.305: IC1.39 27.17,9.39 26.67,8.89
  Top 0.61: 26.67,8.89 25.4,7.62 SV2.7
PL5
  Top 0.305: IC1.40 27.67,8.62 27.3,8.26
  Top 0.61: SV2.8 26.67,3.81 26.67,7.62 27.3,8.26
PL6
  Top 0.305: IC1.41 28.17,7.85 27.94,7.62
  Top 0.61: SV2.9 27.94,7.62
PL7
  Top 0.305: IC1.42 28.67,8.16 29.21,7.62
  Top 0.61: SV2.10 29.21,3.81 29.21,7.62
VCC  (via drill 0.25 pad 0.81)
  Top 0.254: C10.1 39.88,48.88 40.75,49.75 40.75,50.25 42.12,51.62 43.7,51.62 JP1.7
  Top 0.305: IC1.10 21.18,26.9 21.27,26.99 | 30.8,30.8 30.67,30.93 IC1.80 30.67,37.66 31.43,38.42 | IC1.61 32.12,24.4 32.07,24.45 | IC1.31 23.17,20 23.18,20
  Top 0.406: C8.1 16.79,4.08 SV2.1
  Top 0.61: 21.59,20.32 18.73,17.46 C3.1 v18.73,18.41 | C5.1 34.39,33.12 32.07,30.8 | SV3.1 49.53,12.7 v49.53,11.11 50.47,11.11 C9.1 | 32.12,24.4 32.38,24.14 32.38,19.75 34.61,17.52 C4.1 38.09,16.84 39.37,15.56 v39.37,12.7 38.16,13.91 R1.2 | L1.1 4.46,44.39 C7.1 4.46,41.26 SV1.1 6.35,40.64 7.94,39.05 10.48,39.05 16.84,32.69 19.12,32.69 | C10.1 38.72,48.88 SV4.1 38.1,45.09 31.43,38.42 | 21.27,26.99 21.25,27.01 21.25,30.88 19.44,32.69 19.12,32.69 | 19.12,32.69 C6.1
  Bottom 0.254: JP1.4 49,48.88 49,50.75 48.25,51.5 46.66,51.5 JP1.7
  Bottom 0.406: 39.37,12.06 40.32,11.11 v49.53,11.11
  Bottom 0.61: v39.37,12.7 39.37,12.06 | v18.73,18.41 18.73,13.34 16.83,11.43 16.83,10.16 17.78,9.21 17.78,5.62 | 17.78,5.62 SV2.1 | SV5.2 16.5,6.91 17.78,5.62
  pour Top: 20.64,31.43 32.7,31.43 32.7,19.37 20.64,19.37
